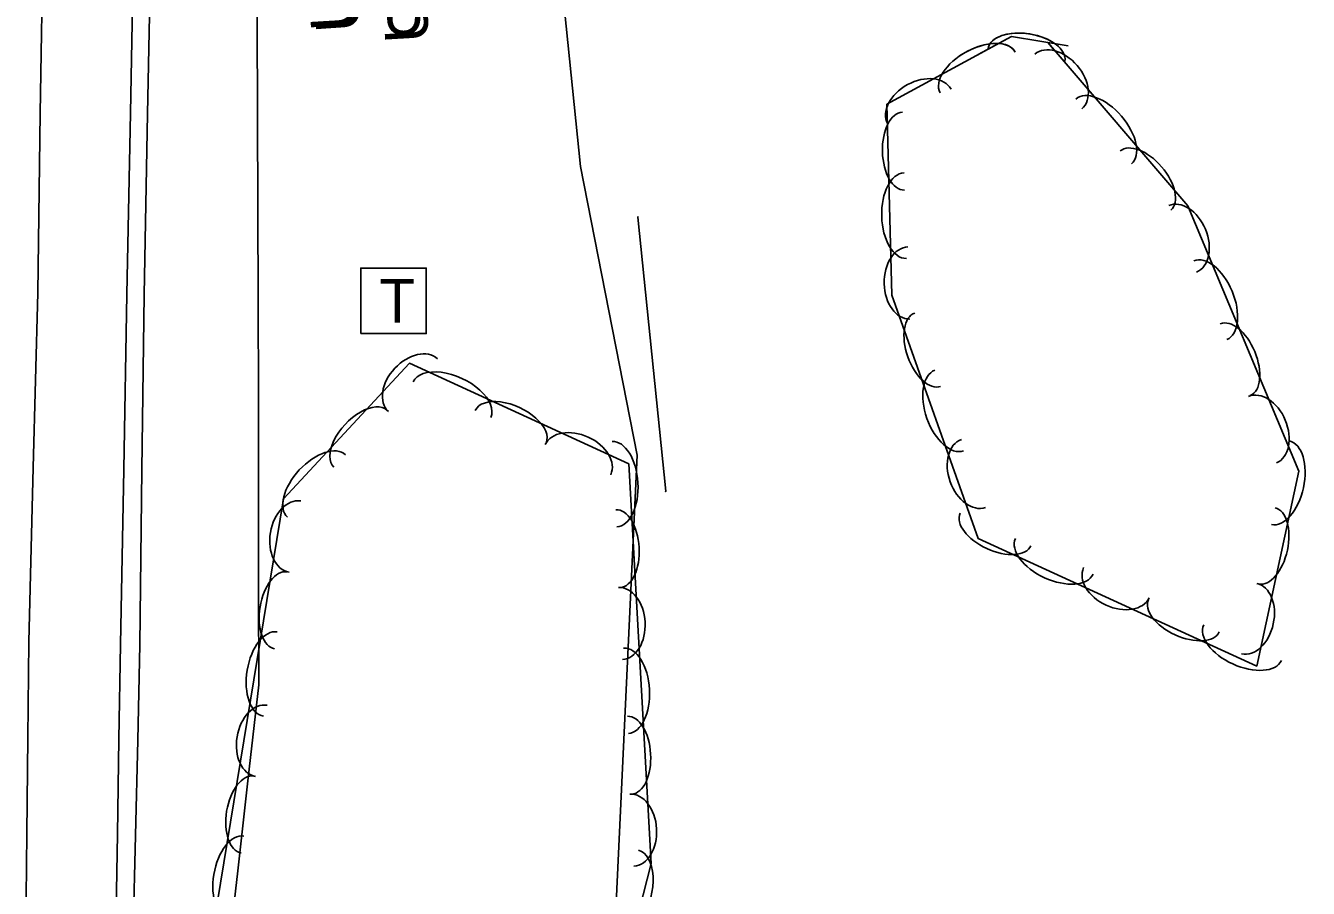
# Model space of a CAD drawing. Extents: x 954793 to 988390, y 1867850 to 1924428.
# Drawn here: x 960975.4 to 961151.5, y 1904787 to 1904905.5 of the extents above; entities that cross this region are included whole.
import ezdxf

# ---------------------------------------------------------------- set-up
doc = ezdxf.new("R2010")
doc.units = 0
for name, color, linetype in [('Default', 7, 'Continuous'), ('S_DITCHLINE', 7, 'Continuous'), ('S_EDGE_PAVEMENT', 7, 'Continuous'), ('S_PAVEMENT_CROWN', 7, 'Continuous'), ('S_SHOULDER', 7, 'Continuous'), ('S_TELEPHONE_UTILITIES', 7, 'Continuous'), ('S_TREE', 7, 'Continuous'), ('S_UTL_PT_SYM', 7, 'Continuous'), ('S_WATER_UTILITIES', 7, 'Continuous')]:
    doc.layers.add(name, color=color, linetype=linetype)

msp = doc.modelspace()

# ---------------------------------------------------------------- linework, layer by layer
at = {"layer": 'S_DITCHLINE'}
msp.add_lwpolyline([(961010.5, 1904943.08), (961007.13, 1904918.76), (961007.18, 1904905.98), (961007.24, 1904893.2), (961007.29, 1904880.41), (961007.35, 1904867.63), (961007.36, 1904854.46), (961007.38, 1904841.29), (961007.39, 1904828.11), (961007.41, 1904814.94), (961005.97, 1904802.16), (961004.53, 1904789.37), (961003.09, 1904776.59), (961001.66, 1904763.8), (961001.03, 1904740.33), (961000.4, 1904716.85), (961001.65, 1904699.9), (961002.89, 1904682.94)], dxfattribs=at)
at = {"layer": 'S_EDGE_PAVEMENT'}
msp.add_lwpolyline([(960990.24, 1904918.32), (960989.78, 1904893.45), (960989.32, 1904868.58), (960988.87, 1904844.53), (960988.42, 1904820.49), (960988.21, 1904807.45), (960988, 1904794.41), (960987.79, 1904781.38)], dxfattribs=at)
at = {"layer": 'S_PAVEMENT_CROWN'}
msp.add_lwpolyline([(960977.79, 1904918.14), (960977.42, 1904893.45), (960977.06, 1904868.76), (960976.45, 1904844.79), (960975.84, 1904820.82), (960975.69, 1904807.66), (960975.55, 1904794.49), (960975.41, 1904781.32)], dxfattribs=at)
msp.add_lwpolyline([(960977.79, 1904918.14), (960977.42, 1904893.45), (960977.06, 1904868.76), (960976.45, 1904844.79), (960975.84, 1904820.82), (960975.69, 1904807.66), (960975.55, 1904794.49), (960975.41, 1904781.32)], dxfattribs=at)
at = {"layer": 'S_SHOULDER'}
msp.add_lwpolyline([(960992.63, 1904918.21), (960992.15, 1904893.36), (960991.66, 1904868.5), (960991.38, 1904844.47), (960991.1, 1904820.43), (960990.79, 1904807.33), (960990.48, 1904794.24), (960990.17, 1904781.14)], dxfattribs=at)
at = {"layer": 'S_TELEPHONE_UTILITIES'}
msp.add_lwpolyline([(961021.42, 1904863.19), (961021.42, 1904872.19), (961030.42, 1904872.19), (961030.42, 1904863.19)], close=True, dxfattribs=at)
at = {"layer": 'S_TREE'}
for points in [[(961115.79, 1904903.13), (961134.97, 1904880.72), (961150.21, 1904844.27), (961144.45, 1904817.5), (961106.18, 1904835.05), (961094.36, 1904868.45), (961093.65, 1904894.68), (961110.76, 1904903.98), (961118.55, 1904902.71)], [(961106.22, 1904901.52), (961110.76, 1904903.98), (961118.55, 1904902.71)], [(961115.79, 1904903.13), (961116.47, 1904902.34)], [(961042.5, 1904716.01), (961026.95, 1904701.53), (961001.13, 1904709.47), (960998.1, 1904762.81), (961010.8, 1904840.49), (961028.12, 1904859.1), (961058.23, 1904845.29), (961061.29, 1904790.37), (961041.7, 1904713.6)]]:
    msp.add_lwpolyline(points, dxfattribs=at)
for centre, major_axis, ratio, start_param, end_param in [((961112.84, 1904901.49), (-5.28, 0.86), 0.5407, 3.141593, 6.283185), ((961112.84, 1904901.49), (-5.28, 0.86), 0.5407, 3.748854, 6.283185), ((961106.13, 1904899.06), (-5.16, -2.8), 0.55008, 3.141593, 6.283185), ((961106.13, 1904899.06), (-5.16, -2.8), 0.55008, 3.163915, 4.902322), ((961117.21, 1904897.81), (-3.22, 3.76), 0.685311, 3.141593, 6.283185), ((961098.12, 1904894.4), (-4.35, -2.37), 0.685311, 3.141593, 6.283185), ((961123.43, 1904890.95), (-3.82, 4.46), 0.55008, 3.141593, 6.283185), ((961095.94, 1904888.24), (0.14, -5.34), 0.540699, 3.141593, 6.283185), ((961129.19, 1904884.21), (-3.48, 4.06), 0.540699, 3.141593, 6.283185), ((961096.18, 1904879.38), (0.16, -5.87), 0.55008, 3.141593, 6.283185), ((961134.27, 1904876.21), (-1.91, 4.57), 0.685311, 3.141593, 6.283185), ((961096.69, 1904870.13), (0.13, -4.95), 0.685311, 3.141593, 6.283185), ((961138.09, 1904867.77), (-2.26, 5.41), 0.55008, 3.141593, 6.283185), ((961099.26, 1904860.97), (1.78, -5.04), 0.540699, 3.141593, 6.283185), ((961141.51, 1904859.59), (-2.06, 4.93), 0.540699, 3.141593, 6.283185), ((961028.58, 1904856.1), (-3.37, -3.63), 0.685611, 3.140713, 6.282305), ((961033.94, 1904854.1), (-5.33, 2.45), 0.550101, 3.141879, 6.283472), ((961102.21, 1904852.61), (1.96, -5.53), 0.55008, 3.141593, 6.283185), ((961145.24, 1904849.98), (-1.91, 4.57), 0.685311, 3.141593, 6.283185), ((961021.38, 1904848.74), (-3.64, -3.91), 0.540936, 3.141072, 6.282665), ((961042, 1904850.4), (-4.86, 2.23), 0.54072, 3.14187, 6.283463), ((961051.25, 1904845.87), (-4.5, 2.07), 0.685337, 3.142062, 6.283654), ((961015.34, 1904842.25), (-3.99, -4.29), 0.550321, 3.141056, 6.282648), ((961056.26, 1904842.5), (-0.33, 5.86), 0.549804, 3.141593, 6.283185), ((961105.55, 1904843.97), (1.65, -4.67), 0.685311, 3.141593, 6.283185), ((961147.7, 1904842.69), (1.24, 5.74), 0.55008, 3.141593, 6.283185), ((961012.37, 1904835.3), (-0.8, -4.89), 0.685, 3.141593, 6.283185), ((961056.76, 1904833.65), (-0.3, 5.34), 0.540428, 3.141593, 6.283185), ((961145.83, 1904834.02), (1.13, 5.23), 0.540699, 3.141593, 6.283185), ((961108.59, 1904836.27), (4.86, -2.23), 0.540699, 3.141593, 6.283185), ((961116.65, 1904832.58), (5.33, -2.45), 0.55008, 3.141593, 6.283185), ((961010.45, 1904825.17), (-0.86, -5.28), 0.540454, 3.141593, 6.283185), ((961125.18, 1904828.96), (4.5, -2.07), 0.685311, 3.141593, 6.283185), ((961057.07, 1904823.35), (-0.28, 4.95), 0.684967, 3.141593, 6.283185), ((961143.41, 1904824.01), (1.04, 4.84), 0.685311, 3.141593, 6.283185), ((961134.44, 1904824.43), (4.86, -2.23), 0.540699, 3.141593, 6.283185), ((961142.5, 1904820.73), (5.33, -2.45), 0.55008, 3.141593, 6.283185), ((961009.01, 1904816.42), (-0.95, -5.79), 0.54983, 3.141593, 6.283185), ((961057.84, 1904814.12), (-0.33, 5.86), 0.549804, 3.141593, 6.283185), ((961007.78, 1904807.24), (-0.8, -4.89), 0.685, 3.141593, 6.283185), ((961058.34, 1904805.27), (-0.3, 5.34), 0.540428, 3.141593, 6.283185), ((961005.86, 1904797.12), (-0.86, -5.28), 0.540454, 3.141593, 6.283185), ((961058.65, 1904794.97), (-0.28, 4.95), 0.684967, 3.141593, 6.283185), ((961004.43, 1904788.37), (-0.95, -5.79), 0.54983, 3.141593, 6.283185), ((961058.12, 1904786.51), (1.45, 5.69), 0.549864, 3.141772, 6.283365)]:
    msp.add_ellipse(centre, major_axis=major_axis, ratio=ratio, start_param=start_param, end_param=end_param, dxfattribs=at)
at = {"layer": 'S_UTL_PT_SYM'}
for points in [[(961051.6, 1904886.13), (961051.6, 1904886.18), (961051.6, 1904886.13), (961051.55, 1904886.13), (961051.6, 1904886.13), (961051.6, 1904886.08), (961051.6, 1904886.13), (961051.65, 1904886.13)], [(961059.48, 1904879.18), (961059.48, 1904879.23), (961059.48, 1904879.18), (961059.43, 1904879.18), (961059.48, 1904879.18), (961059.48, 1904879.13), (961059.48, 1904879.18), (961059.53, 1904879.18)], [(961059.38, 1904846.49), (961059.38, 1904846.54), (961059.38, 1904846.49), (961059.33, 1904846.49), (961059.38, 1904846.49), (961059.38, 1904846.44), (961059.38, 1904846.49), (961059.43, 1904846.49)], [(961063.3, 1904841.53), (961063.3, 1904841.58), (961063.3, 1904841.53), (961063.25, 1904841.53), (961063.3, 1904841.53), (961063.3, 1904841.48), (961063.3, 1904841.53), (961063.35, 1904841.53)]]:
    msp.add_lwpolyline(points, dxfattribs=at)
at = {"layer": 'S_WATER_UTILITIES'}
for p, q in [((961051.6, 1904886.13), (961048.96, 1904911.97)), ((961059.38, 1904846.49), (961051.6, 1904886.13)), ((961063.3, 1904841.53), (961059.48, 1904879.18)), ((961053.43, 1904720.19), (961059.38, 1904846.49))]:
    msp.add_line(p, q, dxfattribs=at)

# ---------------------------------------------------------------- texts
at = {"layer": 'Default'}
for rotation, p in [(93.413, (961020.61, 1904904.99)), (93.8867, (961021.31, 1904904.79)), (360, (961024.42, 1904904.24)), (93.264, (961030.79, 1904903.3))]:
    msp.add_text('U', height=6, rotation=rotation, dxfattribs=at).set_placement(p)
at = {"layer": 'S_TELEPHONE_UTILITIES'}
msp.add_text('T', height=6, rotation=360, dxfattribs=at).set_placement((961023.99, 1904864.69))

doc.saveas('drawing.dxf')
